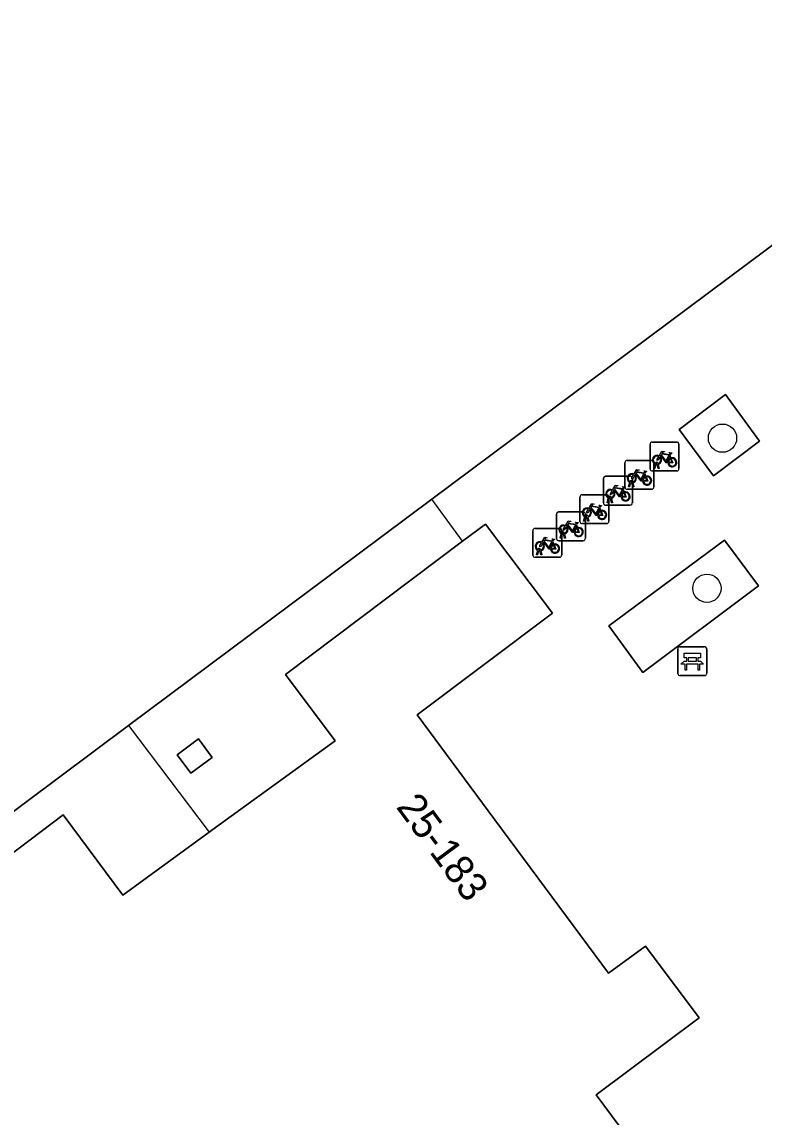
# Model space of a CAD drawing. Extents: x 160663 to 161506, y 382245 to 383291.
# Drawn here: x 161243.57 to 161269.25, y 382615.08 to 382652.94 of the extents above; entities that cross this region are included whole.
import ezdxf

# ---------------------------------------------------------------- set-up
doc = ezdxf.new("R2010")
doc.units = 0
for name, color, linetype in [('IMGEO_Bank', 7, 'Continuous'), ('IMGEO_Boom', 7, 'Continuous'), ('IMGEO_Fietsenrek', 7, 'Continuous'), ('IMGEO_Groenvoorziening', 7, 'Continuous'), ('IMGEO_Pand', 7, 'Continuous'), ('IMGEO_Pand_nummerreeks', 7, 'Continuous'), ('IMGEO_Pand_overbouw', 7, 'Continuous'), ('IMGEO_Voetpad_open', 7, 'Continuous')]:
    doc.layers.add(name, color=color, linetype=linetype)

msp = doc.modelspace()

# ---------------------------------------------------------------- linework, layer by layer
at = {"layer": 'IMGEO_Bank'}
for p, q in [((161266.265, 382630.413), (161266.265, 382631.254)), ((161266.265, 382631.254), (161266.265, 382630.413)), ((161266.34, 382631.338), (161267.181, 382631.338)), ((161267.181, 382631.338), (161266.34, 382631.338)), ((161267.265, 382631.263), (161267.265, 382630.422)), ((161267.265, 382630.422), (161267.265, 382631.263)), ((161266.962, 382630.736), (161266.569, 382630.736)), ((161266.574, 382630.844), (161266.574, 382630.95)), ((161266.618, 382630.95), (161266.618, 382630.844)), ((161266.906, 382630.956), (161266.624, 382630.956)), ((161266.624, 382630.838), (161266.906, 382630.838)), ((161266.912, 382630.844), (161266.912, 382630.95)), ((161266.956, 382630.95), (161266.956, 382630.844)), ((161267.19, 382630.338), (161266.349, 382630.338)), ((161266.349, 382630.338), (161267.19, 382630.338))]:
    msp.add_line(p, q, dxfattribs=at)
for points in [[(161266.568, 382630.956), (161266.482, 382630.956), (161266.482, 382631.117), (161267.045, 382631.117), (161267.045, 382630.956), (161266.962, 382630.956)], [(161266.512, 382630.736), (161266.37, 382630.736), (161266.482, 382630.838), (161266.568, 382630.838)], [(161266.562, 382630.729), (161266.562, 382630.522), (161266.519, 382630.522), (161266.519, 382630.729)], [(161266.962, 382630.838), (161267.045, 382630.838), (161267.157, 382630.736), (161267.018, 382630.736)], [(161267.012, 382630.729), (161267.012, 382630.522), (161266.968, 382630.522), (161266.968, 382630.729)]]:
    msp.add_lwpolyline(points, dxfattribs=at)
for centre, radius, start, end in [((161266.343, 382631.26), 0.0779, 92.4484, 184.2845), ((161266.343, 382631.26), 0.0779, 92.4484, 184.2845), ((161267.187, 382631.26), 0.0779, 2.4484, 94.2845), ((161267.187, 382631.26), 0.0779, 2.4484, 94.2845), ((161266.512, 382630.729), 0.00671, 2.8957, 87.1043), ((161266.569, 382630.729), 0.00671, 92.8957, 177.1043), ((161266.567, 382630.949), 0.00671, 2.8957, 87.1043), ((161266.567, 382630.845), 0.00671, 272.8957, 357.1043), ((161266.624, 382630.949), 0.00671, 92.8957, 177.1043), ((161266.624, 382630.845), 0.00671, 182.8957, 267.1043), ((161266.906, 382630.949), 0.00671, 2.8957, 87.1043), ((161266.906, 382630.845), 0.00671, 272.8957, 357.1043), ((161266.963, 382630.949), 0.00671, 92.8957, 177.1043), ((161266.963, 382630.845), 0.00671, 182.8957, 267.1043), ((161266.961, 382630.729), 0.00671, 2.8957, 87.1043), ((161267.018, 382630.729), 0.00671, 92.8957, 177.1043), ((161266.343, 382630.416), 0.0779, 182.4484, 274.2845), ((161266.343, 382630.416), 0.0779, 182.4484, 274.2845), ((161267.187, 382630.416), 0.0779, 272.4484, 4.2845), ((161267.187, 382630.416), 0.0779, 272.4484, 4.2845)]:
    msp.add_arc(centre, radius, start, end, dxfattribs=at)
at = {"layer": 'IMGEO_Boom'}
for centre in [(161267.81, 382638.547), (161267.271, 382633.358)]:
    msp.add_circle(centre, 0.489, dxfattribs=at)
at = {"layer": 'IMGEO_Fietsenrek'}
for p, q in [((161265.305, 382637.487), (161265.305, 382638.328)), ((161265.305, 382638.328), (161265.305, 382637.487)), ((161265.38, 382638.412), (161266.221, 382638.412)), ((161266.221, 382638.412), (161265.38, 382638.412)), ((161266.305, 382638.337), (161266.305, 382637.496)), ((161266.305, 382637.496), (161266.305, 382638.337)), ((161265.992, 382637.961), (161266.028, 382637.866)), ((161264.434, 382636.854), (161264.434, 382637.695)), ((161264.434, 382637.695), (161264.434, 382636.854)), ((161264.509, 382637.779), (161265.35, 382637.779)), ((161265.35, 382637.779), (161264.509, 382637.779)), ((161265.432, 382637.496), (161265.471, 382637.656)), ((161265.434, 382637.704), (161265.434, 382636.863)), ((161265.434, 382636.863), (161265.434, 382637.704)), ((161265.501, 382637.644), (161265.466, 382637.496)), ((161265.543, 382637.668), (161265.542, 382637.672)), ((161265.584, 382637.496), (161265.55, 382637.638)), ((161265.574, 382637.679), (161265.575, 382637.672)), ((161265.582, 382637.642), (161265.617, 382637.496)), ((161263.691, 382636.307), (161263.691, 382637.148)), ((161263.691, 382637.148), (161263.691, 382636.307)), ((161263.766, 382637.232), (161264.607, 382637.232)), ((161264.607, 382637.232), (161263.766, 382637.232)), ((161264.691, 382637.157), (161264.691, 382636.316)), ((161264.691, 382636.316), (161264.691, 382637.157)), ((161265.121, 382637.328), (161265.157, 382637.233)), ((161266.23, 382637.412), (161265.389, 382637.412)), ((161265.389, 382637.412), (161266.23, 382637.412)), ((161265.466, 382637.496), (161265.432, 382637.496)), ((161265.617, 382637.496), (161265.584, 382637.496)), ((161264.378, 382636.781), (161264.414, 382636.686)), ((161265.359, 382636.779), (161264.518, 382636.779)), ((161264.518, 382636.779), (161265.359, 382636.779)), ((161264.561, 382636.863), (161264.6, 382637.023)), ((161264.595, 382636.863), (161264.561, 382636.863)), ((161264.63, 382637.011), (161264.595, 382636.863)), ((161264.672, 382637.035), (161264.671, 382637.039)), ((161264.713, 382636.863), (161264.679, 382637.005)), ((161264.703, 382637.046), (161264.704, 382637.039)), ((161264.711, 382637.009), (161264.746, 382636.863)), ((161264.746, 382636.863), (161264.713, 382636.863)), ((161262.877, 382635.668), (161262.877, 382636.509)), ((161262.877, 382636.509), (161262.877, 382635.668)), ((161262.952, 382636.593), (161263.793, 382636.593)), ((161263.793, 382636.593), (161262.952, 382636.593)), ((161263.818, 382636.316), (161263.857, 382636.476)), ((161263.887, 382636.464), (161263.852, 382636.316)), ((161263.877, 382636.518), (161263.877, 382635.677)), ((161263.877, 382635.677), (161263.877, 382636.518)), ((161263.929, 382636.488), (161263.928, 382636.492)), ((161263.97, 382636.316), (161263.936, 382636.458)), ((161263.96, 382636.499), (161263.961, 382636.492)), ((161263.968, 382636.462), (161264.003, 382636.316)), ((161262.142, 382636.001), (161262.983, 382636.001)), ((161262.983, 382636.001), (161262.142, 382636.001)), ((161263.564, 382636.142), (161263.6, 382636.047)), ((161264.616, 382636.232), (161263.775, 382636.232)), ((161263.775, 382636.232), (161264.616, 382636.232)), ((161263.852, 382636.316), (161263.818, 382636.316)), ((161264.003, 382636.316), (161263.97, 382636.316)), ((161262.067, 382635.076), (161262.067, 382635.917)), ((161262.067, 382635.917), (161262.067, 382635.076)), ((161263.004, 382635.677), (161263.043, 382635.837)), ((161263.038, 382635.677), (161263.004, 382635.677)), ((161263.073, 382635.825), (161263.038, 382635.677)), ((161263.067, 382635.926), (161263.067, 382635.085)), ((161263.067, 382635.085), (161263.067, 382635.926)), ((161263.115, 382635.849), (161263.114, 382635.853)), ((161263.156, 382635.677), (161263.122, 382635.819)), ((161263.146, 382635.86), (161263.147, 382635.853)), ((161263.154, 382635.823), (161263.189, 382635.677)), ((161263.189, 382635.677), (161263.156, 382635.677)), ((161261.25, 382634.504), (161261.25, 382635.345)), ((161261.25, 382635.345), (161261.25, 382634.504)), ((161261.325, 382635.429), (161262.166, 382635.429)), ((161262.166, 382635.429), (161261.325, 382635.429)), ((161262.194, 382635.085), (161262.233, 382635.245)), ((161262.25, 382635.354), (161262.25, 382634.513)), ((161262.25, 382634.513), (161262.25, 382635.354)), ((161262.305, 382635.257), (161262.304, 382635.261)), ((161262.336, 382635.268), (161262.337, 382635.261)), ((161262.754, 382635.55), (161262.79, 382635.455)), ((161263.802, 382635.593), (161262.961, 382635.593)), ((161262.961, 382635.593), (161263.802, 382635.593)), ((161261.937, 382634.978), (161261.973, 382634.883)), ((161262.992, 382635.001), (161262.151, 382635.001)), ((161262.151, 382635.001), (161262.992, 382635.001)), ((161262.228, 382635.085), (161262.194, 382635.085)), ((161262.263, 382635.233), (161262.228, 382635.085)), ((161262.346, 382635.085), (161262.312, 382635.227)), ((161262.344, 382635.231), (161262.379, 382635.085)), ((161262.379, 382635.085), (161262.346, 382635.085)), ((161261.377, 382634.513), (161261.416, 382634.673)), ((161261.411, 382634.513), (161261.377, 382634.513)), ((161261.446, 382634.661), (161261.411, 382634.513)), ((161261.488, 382634.685), (161261.487, 382634.689)), ((161261.529, 382634.513), (161261.495, 382634.655)), ((161261.519, 382634.696), (161261.52, 382634.689)), ((161261.527, 382634.659), (161261.562, 382634.513)), ((161261.562, 382634.513), (161261.529, 382634.513)), ((161262.175, 382634.429), (161261.334, 382634.429)), ((161261.334, 382634.429), (161262.175, 382634.429))]:
    msp.add_line(p, q, dxfattribs=at)
for points in [[(161265.639, 382637.886), (161265.587, 382637.796), (161265.547, 382637.771), (161265.548, 382637.818), (161265.603, 382637.912)], [(161265.618, 382637.938), (161265.713, 382638.102), (161265.799, 382638.088), (161265.801, 382638.079), (161265.745, 382638.068), (161265.718, 382638.023), (161265.974, 382637.982)], [(161265.914, 382637.694), (161265.864, 382637.694), (161265.673, 382637.945), (161265.654, 382637.913)], [(161265.961, 382637.957), (161265.704, 382637.998), (161265.687, 382637.969), (161265.854, 382637.749), (161265.961, 382637.957)], [(161266.009, 382637.859), (161265.979, 382637.936), (161265.87, 382637.718), (161265.913, 382637.718)], [(161265.974, 382637.982), (161265.999, 382638.031), (161265.993, 382638.035), (161265.97, 382638.039), (161265.958, 382638.046), (161265.957, 382638.049), (161265.959, 382638.054), (161266.054, 382638.039), (161266.056, 382638.029), (161266.046, 382638.016), (161266.034, 382638.01), (161266.02, 382638.016), (161265.992, 382637.961)], [(161265.943, 382637.718), (161266.063, 382637.717), (161266.019, 382637.831)], [(161266.039, 382637.838), (161266.094, 382637.693), (161265.944, 382637.693)], [(161264.768, 382637.253), (161264.716, 382637.163), (161264.676, 382637.138), (161264.677, 382637.185), (161264.732, 382637.279)], [(161264.747, 382637.305), (161264.842, 382637.469), (161264.928, 382637.455), (161264.93, 382637.446), (161264.874, 382637.435), (161264.847, 382637.39), (161265.103, 382637.349)], [(161265.043, 382637.061), (161264.993, 382637.061), (161264.802, 382637.312), (161264.783, 382637.28)], [(161265.09, 382637.324), (161264.833, 382637.365), (161264.816, 382637.336), (161264.983, 382637.116), (161265.09, 382637.324)], [(161265.138, 382637.226), (161265.108, 382637.303), (161264.999, 382637.085), (161265.042, 382637.085)], [(161265.072, 382637.085), (161265.192, 382637.084), (161265.148, 382637.198)], [(161265.168, 382637.205), (161265.223, 382637.06), (161265.073, 382637.06)], [(161265.103, 382637.349), (161265.128, 382637.398), (161265.122, 382637.402), (161265.099, 382637.406), (161265.087, 382637.413), (161265.086, 382637.416), (161265.088, 382637.421), (161265.183, 382637.406), (161265.185, 382637.396), (161265.175, 382637.383), (161265.163, 382637.377), (161265.149, 382637.383), (161265.121, 382637.328)], [(161264.004, 382636.758), (161264.099, 382636.922), (161264.185, 382636.908), (161264.187, 382636.899), (161264.131, 382636.888), (161264.104, 382636.843), (161264.36, 382636.802)], [(161264.3, 382636.514), (161264.25, 382636.514), (161264.059, 382636.765), (161264.04, 382636.733)], [(161264.347, 382636.777), (161264.09, 382636.818), (161264.073, 382636.789), (161264.24, 382636.569), (161264.347, 382636.777)], [(161264.395, 382636.679), (161264.365, 382636.756), (161264.256, 382636.538), (161264.299, 382636.538)], [(161264.36, 382636.802), (161264.385, 382636.851), (161264.379, 382636.855), (161264.356, 382636.859), (161264.344, 382636.866), (161264.343, 382636.869), (161264.345, 382636.874), (161264.44, 382636.859), (161264.442, 382636.849), (161264.432, 382636.836), (161264.42, 382636.83), (161264.406, 382636.836), (161264.378, 382636.781)], [(161264.025, 382636.706), (161263.973, 382636.616), (161263.933, 382636.591), (161263.934, 382636.638), (161263.989, 382636.732)], [(161264.329, 382636.538), (161264.449, 382636.537), (161264.405, 382636.651)], [(161264.425, 382636.658), (161264.48, 382636.513), (161264.33, 382636.513)], [(161263.211, 382636.067), (161263.159, 382635.977), (161263.119, 382635.952), (161263.12, 382635.999), (161263.175, 382636.093)], [(161263.19, 382636.119), (161263.285, 382636.283), (161263.371, 382636.269), (161263.373, 382636.26), (161263.317, 382636.249), (161263.29, 382636.204), (161263.546, 382636.163)], [(161263.486, 382635.875), (161263.436, 382635.875), (161263.245, 382636.126), (161263.226, 382636.094)], [(161263.533, 382636.138), (161263.276, 382636.179), (161263.259, 382636.15), (161263.426, 382635.93), (161263.533, 382636.138)], [(161263.581, 382636.04), (161263.551, 382636.117), (161263.442, 382635.899), (161263.485, 382635.899)], [(161263.515, 382635.899), (161263.635, 382635.898), (161263.591, 382636.012)], [(161263.611, 382636.019), (161263.666, 382635.874), (161263.516, 382635.874)], [(161263.546, 382636.163), (161263.571, 382636.212), (161263.565, 382636.216), (161263.542, 382636.22), (161263.53, 382636.227), (161263.529, 382636.23), (161263.531, 382636.235), (161263.626, 382636.22), (161263.628, 382636.21), (161263.618, 382636.197), (161263.606, 382636.191), (161263.592, 382636.197), (161263.564, 382636.142)], [(161262.38, 382635.527), (161262.475, 382635.691), (161262.561, 382635.677), (161262.563, 382635.668), (161262.507, 382635.657), (161262.48, 382635.612), (161262.736, 382635.571)], [(161262.736, 382635.571), (161262.761, 382635.62), (161262.755, 382635.624), (161262.732, 382635.628), (161262.72, 382635.635), (161262.719, 382635.638), (161262.721, 382635.643), (161262.816, 382635.628), (161262.818, 382635.618), (161262.808, 382635.605), (161262.796, 382635.599), (161262.782, 382635.605), (161262.754, 382635.55)], [(161262.401, 382635.475), (161262.349, 382635.385), (161262.309, 382635.36), (161262.31, 382635.407), (161262.365, 382635.501)], [(161262.676, 382635.283), (161262.626, 382635.283), (161262.435, 382635.534), (161262.416, 382635.502)], [(161262.723, 382635.546), (161262.466, 382635.587), (161262.449, 382635.558), (161262.616, 382635.338), (161262.723, 382635.546)], [(161262.771, 382635.448), (161262.741, 382635.525), (161262.632, 382635.307), (161262.675, 382635.307)], [(161262.705, 382635.307), (161262.825, 382635.306), (161262.781, 382635.42)], [(161262.801, 382635.427), (161262.856, 382635.282), (161262.706, 382635.282)], [(161261.584, 382634.903), (161261.532, 382634.813), (161261.492, 382634.788), (161261.493, 382634.835), (161261.548, 382634.929)], [(161261.563, 382634.955), (161261.658, 382635.119), (161261.744, 382635.105), (161261.746, 382635.096), (161261.69, 382635.085), (161261.663, 382635.04), (161261.919, 382634.999)], [(161261.859, 382634.711), (161261.809, 382634.711), (161261.618, 382634.962), (161261.599, 382634.93)], [(161261.906, 382634.974), (161261.649, 382635.015), (161261.632, 382634.986), (161261.799, 382634.766), (161261.906, 382634.974)], [(161261.954, 382634.876), (161261.924, 382634.953), (161261.815, 382634.735), (161261.858, 382634.735)], [(161261.919, 382634.999), (161261.944, 382635.048), (161261.938, 382635.052), (161261.915, 382635.056), (161261.903, 382635.063), (161261.902, 382635.066), (161261.904, 382635.071), (161261.999, 382635.056), (161262.001, 382635.046), (161261.991, 382635.033), (161261.979, 382635.027), (161261.965, 382635.033), (161261.937, 382634.978)], [(161261.888, 382634.735), (161262.008, 382634.734), (161261.964, 382634.848)], [(161261.984, 382634.855), (161262.039, 382634.71), (161261.889, 382634.71)]]:
    msp.add_lwpolyline(points, dxfattribs=at)
for centre, radius, start, end in [((161265.383, 382638.334), 0.0779, 92.4484, 184.2845), ((161265.383, 382638.334), 0.0779, 92.4484, 184.2845), ((161266.227, 382638.334), 0.0779, 2.4484, 94.2845), ((161266.227, 382638.334), 0.0779, 2.4484, 94.2845), ((161265.545, 382637.797), 0.159, 62.6766, 242.1369), ((161265.545, 382637.797), 0.129, 63.3192, 238.903), ((161265.545, 382637.797), 0.129, 283.6043, 43.4302), ((161265.545, 382637.797), 0.159, 283.5766, 46.6042), ((161264.512, 382637.701), 0.0779, 92.4484, 184.2845), ((161264.512, 382637.701), 0.0779, 92.4484, 184.2845), ((161265.356, 382637.701), 0.0779, 2.4484, 94.2845), ((161265.356, 382637.701), 0.0779, 2.4484, 94.2845), ((161265.525, 382637.668), 0.0499, 12.8025, 158.6934), ((161265.545, 382637.797), 0.159, 253.9967, 271.7867), ((161265.525, 382637.668), 0.0174, 12.8025, 163.4502), ((161265.545, 382637.797), 0.129, 253.415, 269.0204), ((161266.072, 382637.713), 0.159, 113.3408, 178.3217), ((161266.072, 382637.713), 0.159, 187.0065, 105.7708), ((161266.072, 382637.713), 0.129, 113.923, 177.9556), ((161266.072, 382637.713), 0.129, 188.6715, 104.5883), ((161263.769, 382637.154), 0.0779, 92.4484, 184.2845), ((161263.769, 382637.154), 0.0779, 92.4484, 184.2845), ((161264.674, 382637.164), 0.159, 62.6766, 242.1369), ((161264.674, 382637.164), 0.129, 63.3192, 238.903), ((161264.613, 382637.154), 0.0779, 2.4484, 94.2845), ((161264.613, 382637.154), 0.0779, 2.4484, 94.2845), ((161264.674, 382637.164), 0.129, 283.6043, 43.4302), ((161264.674, 382637.164), 0.159, 283.5766, 46.6042), ((161265.201, 382637.08), 0.159, 113.3408, 178.3217), ((161265.201, 382637.08), 0.159, 187.0065, 105.7708), ((161265.201, 382637.08), 0.129, 113.923, 177.9556), ((161265.201, 382637.08), 0.129, 188.6715, 104.5883), ((161265.383, 382637.49), 0.0779, 182.4484, 274.2845), ((161265.383, 382637.49), 0.0779, 182.4484, 274.2845), ((161266.227, 382637.49), 0.0779, 272.4484, 4.2845), ((161266.227, 382637.49), 0.0779, 272.4484, 4.2845), ((161263.931, 382636.617), 0.159, 62.6766, 242.1369), ((161264.512, 382636.857), 0.0779, 182.4484, 274.2845), ((161264.512, 382636.857), 0.0779, 182.4484, 274.2845), ((161264.654, 382637.035), 0.0499, 12.8025, 158.6934), ((161264.674, 382637.164), 0.159, 253.9967, 271.7867), ((161264.654, 382637.035), 0.0174, 12.8025, 163.4502), ((161264.674, 382637.164), 0.129, 253.415, 269.0204), ((161265.356, 382636.857), 0.0779, 272.4484, 4.2845), ((161265.356, 382636.857), 0.0779, 272.4484, 4.2845), ((161262.955, 382636.515), 0.0779, 92.4484, 184.2845), ((161262.955, 382636.515), 0.0779, 92.4484, 184.2845), ((161263.799, 382636.515), 0.0779, 2.4484, 94.2845), ((161263.799, 382636.515), 0.0779, 2.4484, 94.2845), ((161263.931, 382636.617), 0.129, 63.3192, 238.903), ((161263.911, 382636.488), 0.0499, 12.8025, 158.6934), ((161263.931, 382636.617), 0.159, 253.9967, 271.7867), ((161263.911, 382636.488), 0.0174, 12.8025, 163.4502), ((161263.931, 382636.617), 0.129, 253.415, 269.0204), ((161263.931, 382636.617), 0.129, 283.6043, 43.4302), ((161263.931, 382636.617), 0.159, 283.5766, 46.6042), ((161264.458, 382636.533), 0.159, 113.3408, 178.3217), ((161264.458, 382636.533), 0.159, 187.0065, 105.7708), ((161264.458, 382636.533), 0.129, 113.923, 177.9556), ((161264.458, 382636.533), 0.129, 188.6715, 104.5883), ((161262.145, 382635.923), 0.0779, 92.4484, 184.2845), ((161262.145, 382635.923), 0.0779, 92.4484, 184.2845), ((161263.117, 382635.978), 0.159, 62.6766, 242.1369), ((161262.989, 382635.923), 0.0779, 2.4484, 94.2845), ((161262.989, 382635.923), 0.0779, 2.4484, 94.2845), ((161263.117, 382635.978), 0.129, 63.3192, 238.903), ((161263.117, 382635.978), 0.129, 283.6043, 43.4302), ((161263.117, 382635.978), 0.159, 283.5766, 46.6042), ((161263.644, 382635.894), 0.159, 113.3408, 178.3217), ((161263.644, 382635.894), 0.159, 187.0065, 105.7708), ((161263.644, 382635.894), 0.129, 113.923, 177.9556), ((161263.644, 382635.894), 0.129, 188.6715, 104.5883), ((161263.769, 382636.31), 0.0779, 182.4484, 274.2845), ((161263.769, 382636.31), 0.0779, 182.4484, 274.2845), ((161264.613, 382636.31), 0.0779, 272.4484, 4.2845), ((161264.613, 382636.31), 0.0779, 272.4484, 4.2845), ((161262.955, 382635.671), 0.0779, 182.4484, 274.2845), ((161262.955, 382635.671), 0.0779, 182.4484, 274.2845), ((161263.097, 382635.849), 0.0499, 12.8025, 158.6934), ((161263.117, 382635.978), 0.159, 253.9967, 271.7867), ((161263.097, 382635.849), 0.0174, 12.8025, 163.4502), ((161263.117, 382635.978), 0.129, 253.415, 269.0204), ((161263.799, 382635.671), 0.0779, 272.4484, 4.2845), ((161263.799, 382635.671), 0.0779, 272.4484, 4.2845), ((161261.328, 382635.351), 0.0779, 92.4484, 184.2845), ((161261.328, 382635.351), 0.0779, 92.4484, 184.2845), ((161262.307, 382635.386), 0.159, 62.6766, 242.1369), ((161262.172, 382635.351), 0.0779, 2.4484, 94.2845), ((161262.172, 382635.351), 0.0779, 2.4484, 94.2845), ((161262.307, 382635.386), 0.129, 63.3192, 238.903), ((161262.287, 382635.257), 0.0499, 12.8025, 158.6934), ((161262.287, 382635.257), 0.0174, 12.8025, 163.4502), ((161262.307, 382635.386), 0.129, 253.415, 269.0204), ((161262.307, 382635.386), 0.129, 283.6043, 43.4302), ((161262.307, 382635.386), 0.159, 283.5766, 46.6042), ((161262.834, 382635.302), 0.159, 113.3408, 178.3217), ((161262.834, 382635.302), 0.159, 187.0065, 105.7708), ((161262.834, 382635.302), 0.129, 113.923, 177.9556), ((161262.834, 382635.302), 0.129, 188.6715, 104.5883), ((161261.49, 382634.814), 0.159, 62.6766, 242.1369), ((161261.49, 382634.814), 0.129, 63.3192, 238.903), ((161261.49, 382634.814), 0.129, 283.6043, 43.4302), ((161261.49, 382634.814), 0.159, 283.5766, 46.6042), ((161262.017, 382634.73), 0.159, 113.3408, 178.3217), ((161262.017, 382634.73), 0.159, 187.0065, 105.7708), ((161262.017, 382634.73), 0.129, 188.6715, 104.5883), ((161262.145, 382635.079), 0.0779, 182.4484, 274.2845), ((161262.145, 382635.079), 0.0779, 182.4484, 274.2845), ((161262.307, 382635.386), 0.159, 253.9967, 271.7867), ((161262.989, 382635.079), 0.0779, 272.4484, 4.2845), ((161262.989, 382635.079), 0.0779, 272.4484, 4.2845), ((161261.328, 382634.507), 0.0779, 182.4484, 274.2845), ((161261.328, 382634.507), 0.0779, 182.4484, 274.2845), ((161261.47, 382634.685), 0.0499, 12.8025, 158.6934), ((161261.49, 382634.814), 0.159, 253.9967, 271.7867), ((161261.47, 382634.685), 0.0174, 12.8025, 163.4502), ((161261.49, 382634.814), 0.129, 253.415, 269.0204), ((161262.017, 382634.73), 0.129, 113.923, 177.9556), ((161262.172, 382634.507), 0.0779, 272.4484, 4.2845), ((161262.172, 382634.507), 0.0779, 272.4484, 4.2845)]:
    msp.add_arc(centre, radius, start, end, dxfattribs=at)
at = {"layer": 'IMGEO_Groenvoorziening'}
for points in [[(161269.087, 382638.438), (161267.913, 382640.057), (161266.309, 382638.851), (161267.499, 382637.247)], [(161267.883, 382635.025), (161263.877, 382632.064), (161265.055, 382630.445), (161269.06, 382633.443)]]:
    msp.add_lwpolyline(points, close=True, dxfattribs=at)
at = {"layer": 'IMGEO_Pand'}
for points in [[(161238.796, 382622.303), (161247.259, 382628.613), (161253.566, 382633.315), (161257.752, 382636.435), (161272.086, 382647.12), (161272.324, 382647.66), (161272.675, 382647.921), (161279.168, 382652.757), (161272.309, 382661.981), (161274.52, 382663.678), (161272.647, 382666.197), (161272.308, 382665.958), (161269.62, 382669.578), (161266.972, 382673.142), (161263.211, 382678.194), (161261.962, 382679.877), (161260.066, 382678.455), (161259.484, 382679.231), (161238.971, 382663.951)], [(161266.821, 382611.298), (161263.442, 382615.849), (161267.001, 382618.504), (161265.146, 382620.992), (161263.862, 382620.056), (161259.705, 382625.661), (161257.248, 382628.983), (161261.93, 382632.492), (161259.614, 382635.579), (161258.821, 382634.985), (161252.686, 382630.382), (161254.409, 382628.087), (161250.139, 382624.992), (161250.053, 382624.929), (161247.065, 382622.745), (161244.995, 382625.53), (161241.895, 382623.193), (161242.385, 382622.505), (161233.64, 382615.981), (161233.944, 382615.564), (161231.175, 382613.527)]]:
    msp.add_lwpolyline(points, dxfattribs=at)
msp.add_lwpolyline([(161249.682, 382628.152), (161248.945, 382627.606), (161249.421, 382626.962), (161250.158, 382627.508)], close=True, dxfattribs=at)
at = {"layer": 'IMGEO_Pand_overbouw'}
msp.add_lwpolyline([(161247.259, 382628.613), (161250.053, 382624.929), (161250.139, 382624.992), (161254.409, 382628.087), (161252.686, 382630.382), (161258.821, 382634.985), (161257.752, 382636.435), (161253.566, 382633.315)], close=True, dxfattribs=at)
at = {"layer": 'IMGEO_Voetpad_open'}
for points in [[(161275.84, 382643.611), (161272.675, 382647.921), (161272.324, 382647.66), (161272.086, 382647.12), (161257.752, 382636.435), (161253.566, 382633.315), (161247.259, 382628.613), (161238.796, 382622.303), (161231.733, 382631.774), (161230.398, 382630.741), (161231.168, 382629.677), (161226.116, 382625.944), (161228.546, 382622.627), (161226.951, 382621.454), (161228.097, 382619.903), (161223.103, 382616.185), (161215.25, 382610.339)], [(161231.175, 382613.527), (161233.944, 382615.564), (161233.64, 382615.981), (161242.385, 382622.505), (161241.895, 382623.193), (161244.995, 382625.53), (161247.065, 382622.745), (161250.053, 382624.929), (161250.139, 382624.992), (161254.409, 382628.087), (161252.686, 382630.382), (161258.821, 382634.985), (161259.614, 382635.579), (161261.93, 382632.492), (161257.248, 382628.983), (161259.705, 382625.661), (161263.862, 382620.056), (161265.146, 382620.992), (161267.001, 382618.504), (161263.442, 382615.849), (161266.821, 382611.298)]]:
    msp.add_lwpolyline(points, dxfattribs=at)
for points in [[(161266.309, 382638.851), (161267.913, 382640.057), (161269.087, 382638.438), (161267.499, 382637.247)], [(161267.883, 382635.025), (161269.06, 382633.443), (161265.055, 382630.445), (161263.877, 382632.064)], [(161248.945, 382627.606), (161249.682, 382628.152), (161250.158, 382627.508), (161249.421, 382626.962)]]:
    msp.add_lwpolyline(points, close=True, dxfattribs=at)

# ---------------------------------------------------------------- texts
at = {"layer": 'IMGEO_Pand_nummerreeks'}
msp.add_text('25-183', height=1, rotation=306.5602, dxfattribs=at).set_placement((161256.494, 382625.795))

doc.saveas('drawing.dxf')
